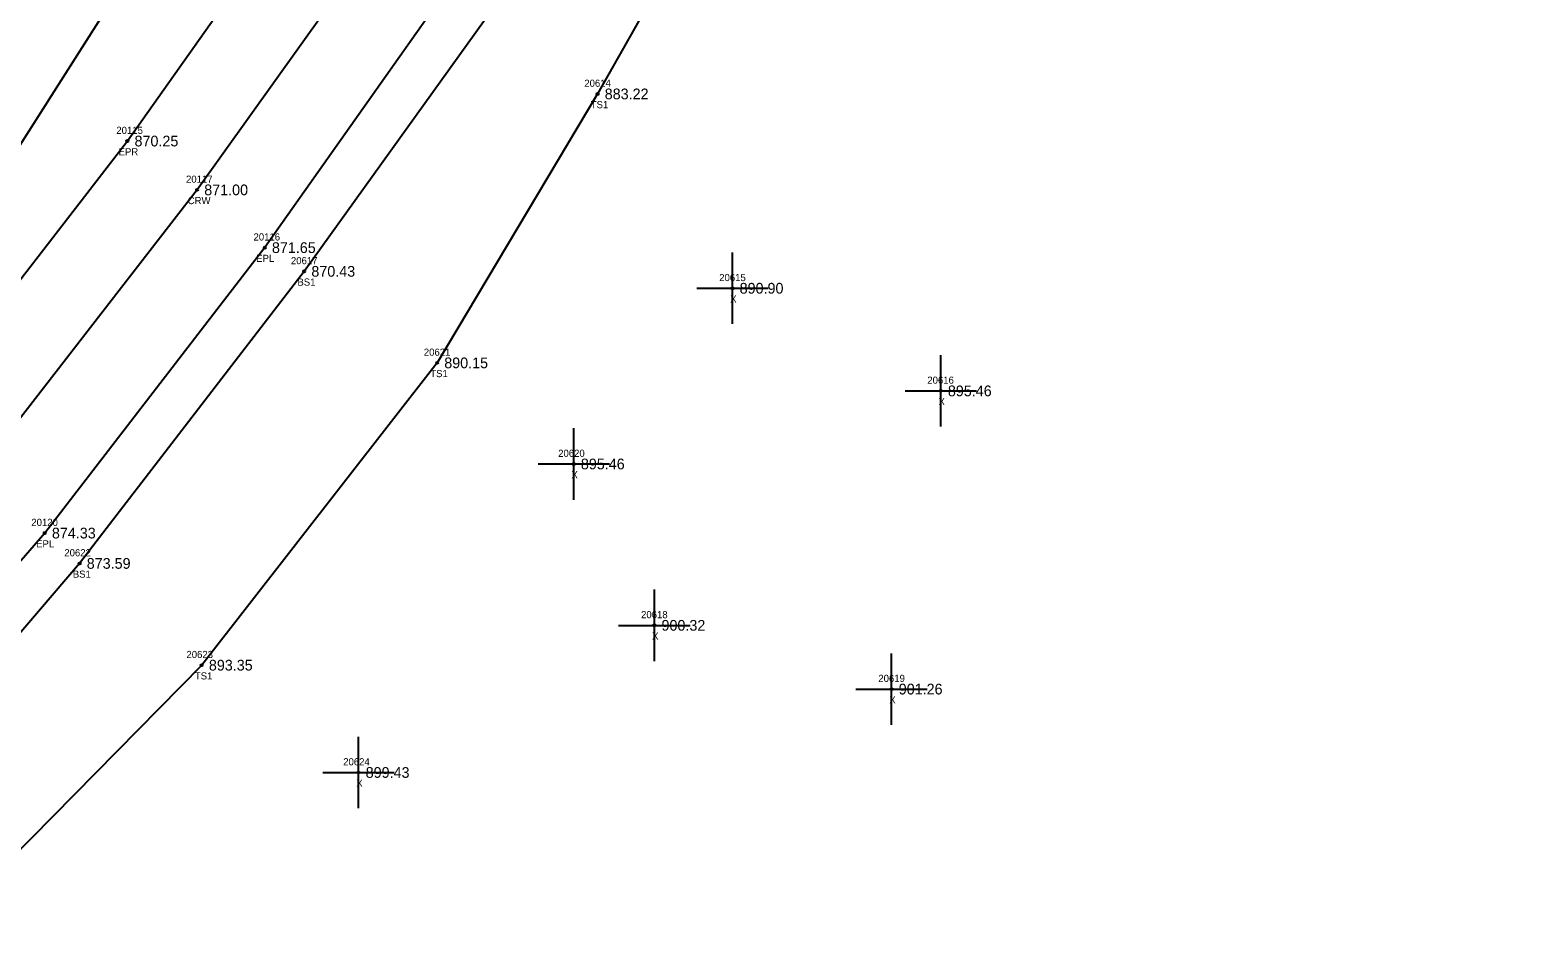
# Model space of a CAD drawing. Extents: x 1394668 to 1397182, y 1073212 to 1074501.
# Drawn here: x 1395697.6 to 1395908.7, y 1073559.6 to 1073687.4 of the extents above; entities that cross this region are included whole.
import ezdxf

# ---------------------------------------------------------------- set-up
doc = ezdxf.new("R2010")
doc.units = 0
for name, color, linetype in [('RD_DTM_BkLn1', 7, 'Continuous'), ('RD_DTM_BkLn2', 7, 'Continuous'), ('RD_DTM_BkLn_txCode', 7, 'Continuous'), ('RD_EX_Misc', 7, 'Continuous'), ('RD_EX_Misc_txCode', 7, 'Continuous'), ('RD_EX_Road', 7, 'Continuous'), ('RD_EX_Road_txCode', 7, 'Continuous'), ('RD_EX_TX_Misc_ELEV', 7, 'Continuous'), ('RD_EX_TX_Road_ELEV', 7, 'Continuous'), ('RD_HC_Survey_ELEV', 7, 'Continuous'), ('RD_HC_Survey_txCode', 7, 'Continuous'), ('RD_SMD_Locator', 7, 'Continuous')]:
    doc.layers.add(name, color=color, linetype=linetype)

msp = doc.modelspace()

# ---------------------------------------------------------------- linework, layer by layer
at = {"layer": 'RD_DTM_BkLn1'}
msp.add_lwpolyline([(1395880.09, 1073905.01), (1395858.99, 1073872.06), (1395832.15, 1073830.06), (1395805.49, 1073788.39), (1395778.2, 1073746.79), (1395749.91, 1073705.5), (1395721.01, 1073665.07), (1395690.33, 1073625.47), (1395658.02, 1073587.64), (1395622.95, 1073551.76), (1395585.52, 1073519.1), (1395545.34, 1073489.25), (1395503.34, 1073462.75), (1395459.17, 1073438.88), (1395413.72, 1073418.7), (1395366.56, 1073401.38), (1395319.05, 1073387), (1395269.86, 1073375.63), (1395220.56, 1073368.3)], dxfattribs=at)
at = {"layer": 'RD_DTM_BkLn2'}
for points in [[(1395872.29, 1073920.9), (1395859.76, 1073907.25), (1395840.82, 1073914.9), (1395825.1, 1073901.57), (1395832.07, 1073866.74), (1395834.98, 1073863.18), (1395809.97, 1073825.37), (1395786.91, 1073785.27), (1395760.58, 1073746.02), (1395733.77, 1073707.72), (1395713.02, 1073697.84), (1395686.96, 1073656.85), (1395662.51, 1073616.18), (1395631.74, 1073579.72), (1395598.58, 1073547.6), (1395556.36, 1073515.78), (1395517.25, 1073487.44)], [(1395908.34, 1073750.37), (1395886.37, 1073772.78), (1395863.64, 1073802.73), (1395854.1, 1073805.01), (1395826.05, 1073773.11), (1395793.87, 1073734.05), (1395764.78, 1073693.78), (1395736.01, 1073653.66), (1395704.56, 1073612.75), (1395670.33, 1073572.71), (1395637.43, 1073538.26), (1395595.47, 1073500.49), (1395545.21, 1073467.28)], [(1395908.75, 1073745.01), (1395882.18, 1073769.9), (1395863.69, 1073800.73), (1395855.74, 1073800.14), (1395835.34, 1073770.65), (1395805.16, 1073728.22), (1395777.09, 1073678.51), (1395754.62, 1073640.84), (1395721.66, 1073598.5), (1395682.88, 1073559.13), (1395644.57, 1073530.52), (1395608.93, 1073486.25), (1395561.12, 1073435.87)]]:
    msp.add_lwpolyline(points, dxfattribs=at)
at = {"layer": 'RD_EX_Misc'}
for p, q in [((1395795.98, 1073646.29), (1395795.98, 1073656.29)), ((1395790.98, 1073651.29), (1395800.98, 1073651.29)), ((1395825.14, 1073631.92), (1395825.14, 1073641.92)), ((1395820.14, 1073636.92), (1395830.14, 1073636.92)), ((1395773.75, 1073621.68), (1395773.75, 1073631.68)), ((1395768.75, 1073626.68), (1395778.75, 1073626.68)), ((1395785.04, 1073599.08), (1395785.04, 1073609.08)), ((1395780.04, 1073604.08), (1395790.04, 1073604.08)), ((1395818.26, 1073590.15), (1395818.26, 1073600.15)), ((1395813.26, 1073595.15), (1395823.26, 1073595.15)), ((1395743.62, 1073578.47), (1395743.62, 1073588.47)), ((1395738.62, 1073583.47), (1395748.62, 1073583.47))]:
    msp.add_line(p, q, dxfattribs=at)
at = {"layer": 'RD_EX_Road'}
for points in [[(1395869.55, 1073911.71), (1395848.71, 1073878.81), (1395821.89, 1073836.43), (1395795.02, 1073794.57), (1395768.15, 1073753.29), (1395739.4, 1073711.73), (1395711.25, 1073671.91), (1395680.67, 1073632.3), (1395648.91, 1073595.47), (1395613.89, 1073559.5), (1395578.15, 1073528.43), (1395538.64, 1073499.26), (1395497.33, 1073473.22), (1395453.33, 1073449.12), (1395408.97, 1073429.57), (1395362.04, 1073412.34), (1395315.46, 1073398.44), (1395267.16, 1073387.31), (1395218.96, 1073380.11)], [(1395889.95, 1073898.5), (1395869.5, 1073865.35), (1395861.01, 1073852.28), (1395854.66, 1073843.33), (1395841.6, 1073823.61), (1395818.72, 1073786.86), (1395788.22, 1073740.4), (1395759.3, 1073697.79), (1395730.49, 1073656.98), (1395699.68, 1073617), (1395667.2, 1073579.48), (1395631.87, 1073543.45), (1395592.83, 1073509.92), (1395550.91, 1073478.97), (1395509.01, 1073452.5), (1395464.5, 1073428.26), (1395417.91, 1073407.56), (1395369.36, 1073389.54), (1395322.83, 1073375.66), (1395271.04, 1073363.5), (1395222.14, 1073356.32)]]:
    msp.add_lwpolyline(points, dxfattribs=at)
at = {"layer": 'RD_SMD_Locator'}
for centre in [(1395777.09, 1073678.51), (1395711.25, 1073671.91), (1395721.01, 1073665.07), (1395730.49, 1073656.98), (1395736.01, 1073653.66), (1395795.98, 1073651.29), (1395754.62, 1073640.84), (1395825.14, 1073636.92), (1395773.75, 1073626.68), (1395699.68, 1073617), (1395704.56, 1073612.75), (1395785.04, 1073604.08), (1395721.66, 1073598.5), (1395818.26, 1073595.15), (1395743.62, 1073583.47)]:
    msp.add_circle(centre, 0.15, dxfattribs=at)

# ---------------------------------------------------------------- texts
at = {"layer": 'RD_DTM_BkLn_txCode'}
for s, p in [('20614', (1395775.23, 1073679.51)), ('TS1', (1395776.13, 1073676.51)), ('20617', (1395734.15, 1073654.66)), ('BS1', (1395735.06, 1073651.66)), ('20621', (1395752.76, 1073641.84)), ('TS1', (1395753.66, 1073638.84)), ('20622', (1395702.42, 1073613.75)), ('BS1', (1395703.61, 1073610.75)), ('20623', (1395719.52, 1073599.5)), ('TS1', (1395720.7, 1073596.5))]:
    msp.add_text(s, height=1, dxfattribs=at).set_placement(p)
at = {"layer": 'RD_EX_Misc_txCode'}
for s, p in [('20615', (1395794.12, 1073652.29)), ('X', (1395795.66, 1073649.29)), ('20616', (1395823.26, 1073637.92)), ('X', (1395824.83, 1073634.92)), ('20620', (1395771.57, 1073627.68)), ('X', (1395773.43, 1073624.68)), ('20618', (1395783.18, 1073605.08)), ('X', (1395784.72, 1073602.08)), ('20619', (1395816.4, 1073596.15)), ('X', (1395817.94, 1073593.15)), ('20624', (1395741.47, 1073584.47)), ('X', (1395743.3, 1073581.47))]:
    msp.add_text(s, height=1, dxfattribs=at).set_placement(p)
at = {"layer": 'RD_EX_Road_txCode'}
for s, p in [('20115', (1395709.7, 1073672.91)), ('EPR', (1395710.02, 1073669.91)), ('20116', (1395728.91, 1073657.98)), ('EPL', (1395729.28, 1073654.98)), ('20120', (1395697.8, 1073618)), ('EPL', (1395698.47, 1073615))]:
    msp.add_text(s, height=1, dxfattribs=at).set_placement(p)
at = {"layer": 'RD_EX_TX_Misc_ELEV'}
for s, p in [('883.22', (1395778.09, 1073677.76)), ('870.43', (1395737.01, 1073652.91)), ('890.90', (1395796.98, 1073650.54)), ('890.15', (1395755.62, 1073640.09)), ('895.46', (1395826.14, 1073636.17)), ('895.46', (1395774.75, 1073625.93)), ('873.59', (1395705.56, 1073612)), ('900.32', (1395786.04, 1073603.33)), ('893.35', (1395722.66, 1073597.75)), ('901.26', (1395819.26, 1073594.4)), ('899.43', (1395744.62, 1073582.72))]:
    msp.add_text(s, height=1.5, dxfattribs=at).set_placement(p)
at = {"layer": 'RD_EX_TX_Road_ELEV'}
for s, p in [('870.25', (1395712.25, 1073671.16)), ('871.65', (1395731.49, 1073656.23)), ('874.33', (1395700.68, 1073616.25))]:
    msp.add_text(s, height=1.5, dxfattribs=at).set_placement(p)
at = {"layer": 'RD_HC_Survey_ELEV'}
msp.add_text('871.00', height=1.5, dxfattribs=at).set_placement((1395722.01, 1073664.32))
at = {"layer": 'RD_HC_Survey_txCode'}
for s, p in [('20117', (1395719.46, 1073666.07)), ('CRW', (1395719.7, 1073663.07))]:
    msp.add_text(s, height=1, dxfattribs=at).set_placement(p)

doc.saveas('drawing.dxf')
